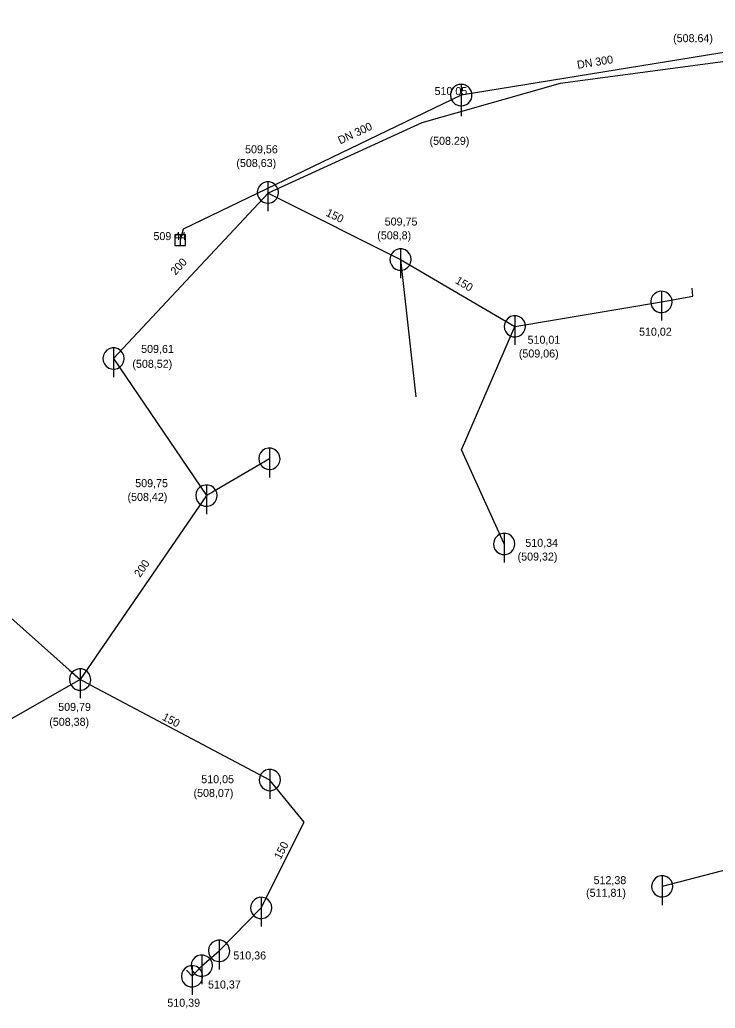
# Model space of a CAD drawing. Extents: x -476058 to -471893, y -1155786 to -1152000.
# Drawn here: x -475058.6 to -474993.4, y -1154259.7 to -1154167.1 of the extents above; entities that cross this region are included whole.
import ezdxf

# ---------------------------------------------------------------- set-up
doc = ezdxf.new("R2010")
doc.units = 0
for name, color, linetype in [('Vrstva 1', 7, 'Continuous'), ('Vrstva 10', 7, 'Continuous'), ('Vrstva 16', 7, 'Continuous'), ('Vrstva 18', 7, 'Continuous'), ('Vrstva 19', 7, 'Continuous'), ('Vrstva 3', 7, 'Continuous'), ('Vrstva 35', 7, 'Continuous'), ('Vrstva 4', 7, 'Continuous'), ('Vrstva 45', 7, 'Continuous'), ('Vrstva 50', 7, 'Continuous'), ('Vrstva 51', 7, 'Continuous')]:
    doc.layers.add(name, color=color, linetype=linetype)

msp = doc.modelspace()

# ---------------------------------------------------------------- linework, layer by layer
at = {"layer": 'Vrstva 1'}
for p, q in [((-475017.24, -1154174.14), (-475017.24, -1154174.14)), ((-475043.32, -1154186.7), (-475043.32, -1154186.7)), ((-475043.59, -1154187.73), (-475043.59, -1154187.73))]:
    msp.add_line(p, q, dxfattribs=at)
at = {"layer": 'Vrstva 10'}
for p, q in [((-475035.36, -1154182.27), (-475035.36, -1154185.018)), ((-475043.59, -1154187.23), (-475043.59, -1154188.23)), ((-475022.928, -1154188.55), (-475022.928, -1154191.298)), ((-474998.47, -1154192.52), (-474998.47, -1154195.268)), ((-475012.21, -1154194.81), (-475012.21, -1154197.558)), ((-475049.834, -1154197.823), (-475049.834, -1154200.571)), ((-475035.222, -1154207.219), (-475035.222, -1154209.967)), ((-475041.12, -1154210.67), (-475041.12, -1154213.418)), ((-475013.214, -1154215.203), (-475013.214, -1154217.951)), ((-475052.97, -1154227.9), (-475052.97, -1154230.648)), ((-475035.18, -1154237.32), (-475035.18, -1154240.068)), ((-474998.4, -1154247.28), (-474998.4, -1154250.028)), ((-475035.987, -1154249.299), (-475035.987, -1154252.047)), ((-475039.938, -1154253.32), (-475039.938, -1154256.068)), ((-475041.56, -1154254.712), (-475041.56, -1154257.46)), ((-475042.476, -1154255.709), (-475042.476, -1154258.457))]:
    msp.add_line(p, q, dxfattribs=at)
for points in [[(-475016.232, -1154174.14), (-475016.238, -1154174.035), (-475016.254, -1154173.931), (-475016.282, -1154173.829), (-475016.32, -1154173.73), (-475016.367, -1154173.636), (-475016.425, -1154173.548), (-475016.491, -1154173.466), (-475016.566, -1154173.391), (-475016.648, -1154173.325), (-475016.736, -1154173.267), (-475016.83, -1154173.22), (-475016.929, -1154173.182), (-475017.031, -1154173.154), (-475017.135, -1154173.138), (-475017.24, -1154173.132), (-475017.345, -1154173.138), (-475017.45, -1154173.154), (-475017.552, -1154173.182), (-475017.65, -1154173.22), (-475017.744, -1154173.267), (-475017.833, -1154173.325), (-475017.915, -1154173.391), (-475017.989, -1154173.466), (-475018.055, -1154173.548), (-475018.113, -1154173.636), (-475018.161, -1154173.73), (-475018.199, -1154173.829), (-475018.226, -1154173.931), (-475018.242, -1154174.035), (-475018.248, -1154174.14), (-475018.242, -1154174.245), (-475018.226, -1154174.35), (-475018.199, -1154174.452), (-475018.161, -1154174.55), (-475018.113, -1154174.644), (-475018.055, -1154174.733), (-475017.989, -1154174.815), (-475017.915, -1154174.889), (-475017.833, -1154174.955), (-475017.744, -1154175.013), (-475017.65, -1154175.061), (-475017.552, -1154175.099), (-475017.45, -1154175.126), (-475017.345, -1154175.142), (-475017.24, -1154175.148), (-475017.135, -1154175.142), (-475017.031, -1154175.126), (-475016.929, -1154175.099), (-475016.83, -1154175.061), (-475016.736, -1154175.013), (-475016.648, -1154174.955), (-475016.566, -1154174.889), (-475016.491, -1154174.815), (-475016.425, -1154174.733), (-475016.367, -1154174.644), (-475016.32, -1154174.55), (-475016.282, -1154174.452), (-475016.254, -1154174.35), (-475016.238, -1154174.245), (-475016.232, -1154174.14)], [(-475017.24, -1154173.132), (-475017.24, -1154176.108)], [(-475034.36, -1154183.27), (-475034.399, -1154182.991), (-475034.516, -1154182.734), (-475034.699, -1154182.519), (-475034.935, -1154182.365), (-475035.205, -1154182.282), (-475035.487, -1154182.278), (-475035.759, -1154182.353), (-475035.999, -1154182.501), (-475036.189, -1154182.71), (-475036.312, -1154182.964), (-475036.36, -1154183.242), (-475036.328, -1154183.523), (-475036.219, -1154183.783), (-475036.041, -1154184.002), (-475035.81, -1154184.164), (-475035.542, -1154184.254), (-475035.26, -1154184.266), (-475034.986, -1154184.198), (-475034.742, -1154184.057), (-475034.547, -1154183.853), (-475034.417, -1154183.603), (-475034.361, -1154183.326), (-475034.36, -1154183.27)], [(-475021.928, -1154189.55), (-475021.967, -1154189.271), (-475022.084, -1154189.014), (-475022.267, -1154188.799), (-475022.503, -1154188.645), (-475022.773, -1154188.562), (-475023.055, -1154188.558), (-475023.327, -1154188.633), (-475023.567, -1154188.781), (-475023.757, -1154188.99), (-475023.88, -1154189.244), (-475023.928, -1154189.522), (-475023.896, -1154189.803), (-475023.787, -1154190.063), (-475023.609, -1154190.282), (-475023.378, -1154190.444), (-475023.11, -1154190.534), (-475022.828, -1154190.546), (-475022.554, -1154190.478), (-475022.31, -1154190.337), (-475022.115, -1154190.133), (-475021.985, -1154189.883), (-475021.929, -1154189.606), (-475021.928, -1154189.55)], [(-474997.47, -1154193.52), (-474997.509, -1154193.241), (-474997.626, -1154192.984), (-474997.809, -1154192.769), (-474998.045, -1154192.615), (-474998.315, -1154192.532), (-474998.597, -1154192.528), (-474998.869, -1154192.603), (-474999.109, -1154192.751), (-474999.299, -1154192.96), (-474999.422, -1154193.214), (-474999.47, -1154193.492), (-474999.438, -1154193.773), (-474999.329, -1154194.033), (-474999.151, -1154194.252), (-474998.92, -1154194.414), (-474998.652, -1154194.504), (-474998.37, -1154194.516), (-474998.096, -1154194.448), (-474997.852, -1154194.307), (-474997.657, -1154194.103), (-474997.527, -1154193.853), (-474997.471, -1154193.576), (-474997.47, -1154193.52)], [(-475011.21, -1154195.81), (-475011.249, -1154195.531), (-475011.366, -1154195.274), (-475011.549, -1154195.059), (-475011.785, -1154194.905), (-475012.055, -1154194.822), (-475012.337, -1154194.818), (-475012.609, -1154194.893), (-475012.849, -1154195.041), (-475013.039, -1154195.25), (-475013.162, -1154195.504), (-475013.21, -1154195.782), (-475013.178, -1154196.063), (-475013.069, -1154196.323), (-475012.891, -1154196.542), (-475012.66, -1154196.704), (-475012.392, -1154196.794), (-475012.11, -1154196.806), (-475011.836, -1154196.738), (-475011.592, -1154196.597), (-475011.397, -1154196.393), (-475011.267, -1154196.143), (-475011.211, -1154195.866), (-475011.21, -1154195.81)], [(-475048.834, -1154198.823), (-475048.873, -1154198.544), (-475048.99, -1154198.287), (-475049.173, -1154198.072), (-475049.409, -1154197.918), (-475049.679, -1154197.835), (-475049.961, -1154197.831), (-475050.233, -1154197.906), (-475050.473, -1154198.054), (-475050.663, -1154198.263), (-475050.786, -1154198.517), (-475050.834, -1154198.795), (-475050.802, -1154199.076), (-475050.693, -1154199.336), (-475050.515, -1154199.555), (-475050.284, -1154199.717), (-475050.016, -1154199.807), (-475049.734, -1154199.819), (-475049.46, -1154199.751), (-475049.216, -1154199.61), (-475049.021, -1154199.406), (-475048.891, -1154199.156), (-475048.835, -1154198.879), (-475048.834, -1154198.823)], [(-475034.222, -1154208.219), (-475034.261, -1154207.94), (-475034.378, -1154207.683), (-475034.561, -1154207.468), (-475034.797, -1154207.314), (-475035.067, -1154207.231), (-475035.349, -1154207.227), (-475035.621, -1154207.302), (-475035.861, -1154207.45), (-475036.051, -1154207.659), (-475036.174, -1154207.913), (-475036.222, -1154208.191), (-475036.19, -1154208.472), (-475036.081, -1154208.732), (-475035.903, -1154208.951), (-475035.672, -1154209.113), (-475035.404, -1154209.203), (-475035.122, -1154209.215), (-475034.848, -1154209.147), (-475034.604, -1154209.006), (-475034.409, -1154208.802), (-475034.279, -1154208.552), (-475034.223, -1154208.275), (-475034.222, -1154208.219)], [(-475040.12, -1154211.67), (-475040.159, -1154211.391), (-475040.276, -1154211.134), (-475040.459, -1154210.919), (-475040.695, -1154210.765), (-475040.965, -1154210.682), (-475041.247, -1154210.678), (-475041.519, -1154210.753), (-475041.759, -1154210.901), (-475041.949, -1154211.11), (-475042.072, -1154211.364), (-475042.12, -1154211.642), (-475042.088, -1154211.923), (-475041.979, -1154212.183), (-475041.801, -1154212.402), (-475041.57, -1154212.564), (-475041.302, -1154212.654), (-475041.02, -1154212.666), (-475040.746, -1154212.598), (-475040.502, -1154212.457), (-475040.307, -1154212.253), (-475040.177, -1154212.003), (-475040.121, -1154211.726), (-475040.12, -1154211.67)], [(-475012.214, -1154216.203), (-475012.253, -1154215.924), (-475012.37, -1154215.667), (-475012.553, -1154215.452), (-475012.789, -1154215.298), (-475013.059, -1154215.215), (-475013.341, -1154215.211), (-475013.613, -1154215.286), (-475013.853, -1154215.434), (-475014.043, -1154215.643), (-475014.166, -1154215.897), (-475014.214, -1154216.175), (-475014.182, -1154216.456), (-475014.073, -1154216.716), (-475013.895, -1154216.935), (-475013.664, -1154217.097), (-475013.396, -1154217.187), (-475013.114, -1154217.199), (-475012.84, -1154217.131), (-475012.596, -1154216.99), (-475012.401, -1154216.786), (-475012.271, -1154216.536), (-475012.215, -1154216.259), (-475012.214, -1154216.203)], [(-475051.97, -1154228.9), (-475052.009, -1154228.621), (-475052.126, -1154228.364), (-475052.309, -1154228.149), (-475052.545, -1154227.995), (-475052.815, -1154227.912), (-475053.097, -1154227.908), (-475053.369, -1154227.983), (-475053.609, -1154228.131), (-475053.799, -1154228.34), (-475053.922, -1154228.594), (-475053.97, -1154228.872), (-475053.938, -1154229.153), (-475053.829, -1154229.413), (-475053.651, -1154229.632), (-475053.42, -1154229.794), (-475053.152, -1154229.884), (-475052.87, -1154229.896), (-475052.596, -1154229.828), (-475052.352, -1154229.687), (-475052.157, -1154229.483), (-475052.027, -1154229.233), (-475051.971, -1154228.956), (-475051.97, -1154228.9)], [(-475034.18, -1154238.32), (-475034.219, -1154238.041), (-475034.336, -1154237.784), (-475034.519, -1154237.569), (-475034.755, -1154237.415), (-475035.025, -1154237.332), (-475035.307, -1154237.328), (-475035.579, -1154237.403), (-475035.819, -1154237.551), (-475036.009, -1154237.76), (-475036.132, -1154238.014), (-475036.18, -1154238.292), (-475036.148, -1154238.573), (-475036.039, -1154238.833), (-475035.861, -1154239.052), (-475035.63, -1154239.214), (-475035.362, -1154239.304), (-475035.08, -1154239.316), (-475034.806, -1154239.248), (-475034.562, -1154239.107), (-475034.367, -1154238.903), (-475034.237, -1154238.653), (-475034.181, -1154238.376), (-475034.18, -1154238.32)], [(-474997.4, -1154248.28), (-474997.439, -1154248.001), (-474997.556, -1154247.744), (-474997.739, -1154247.529), (-474997.975, -1154247.375), (-474998.245, -1154247.292), (-474998.527, -1154247.288), (-474998.799, -1154247.363), (-474999.039, -1154247.511), (-474999.229, -1154247.72), (-474999.352, -1154247.974), (-474999.4, -1154248.252), (-474999.368, -1154248.533), (-474999.259, -1154248.793), (-474999.081, -1154249.012), (-474998.85, -1154249.174), (-474998.582, -1154249.264), (-474998.3, -1154249.276), (-474998.026, -1154249.208), (-474997.782, -1154249.067), (-474997.587, -1154248.863), (-474997.457, -1154248.613), (-474997.401, -1154248.336), (-474997.4, -1154248.28)], [(-475034.987, -1154250.299), (-475035.026, -1154250.02), (-475035.143, -1154249.763), (-475035.326, -1154249.548), (-475035.562, -1154249.394), (-475035.832, -1154249.311), (-475036.114, -1154249.307), (-475036.386, -1154249.382), (-475036.626, -1154249.53), (-475036.816, -1154249.739), (-475036.939, -1154249.993), (-475036.987, -1154250.271), (-475036.955, -1154250.552), (-475036.846, -1154250.812), (-475036.668, -1154251.031), (-475036.437, -1154251.193), (-475036.169, -1154251.283), (-475035.887, -1154251.295), (-475035.613, -1154251.227), (-475035.369, -1154251.086), (-475035.174, -1154250.882), (-475035.044, -1154250.632), (-475034.988, -1154250.355), (-475034.987, -1154250.299)], [(-475038.938, -1154254.32), (-475038.977, -1154254.041), (-475039.094, -1154253.784), (-475039.277, -1154253.569), (-475039.513, -1154253.415), (-475039.783, -1154253.332), (-475040.065, -1154253.328), (-475040.337, -1154253.403), (-475040.577, -1154253.551), (-475040.767, -1154253.76), (-475040.89, -1154254.014), (-475040.938, -1154254.292), (-475040.906, -1154254.573), (-475040.797, -1154254.833), (-475040.619, -1154255.052), (-475040.388, -1154255.214), (-475040.12, -1154255.304), (-475039.838, -1154255.316), (-475039.564, -1154255.248), (-475039.32, -1154255.107), (-475039.125, -1154254.903), (-475038.995, -1154254.653), (-475038.939, -1154254.376), (-475038.938, -1154254.32)], [(-475040.56, -1154255.712), (-475040.599, -1154255.433), (-475040.716, -1154255.176), (-475040.899, -1154254.961), (-475041.135, -1154254.807), (-475041.405, -1154254.724), (-475041.687, -1154254.72), (-475041.959, -1154254.795), (-475042.199, -1154254.943), (-475042.389, -1154255.152), (-475042.512, -1154255.406), (-475042.56, -1154255.684), (-475042.528, -1154255.965), (-475042.419, -1154256.225), (-475042.241, -1154256.444), (-475042.01, -1154256.606), (-475041.742, -1154256.696), (-475041.46, -1154256.708), (-475041.186, -1154256.64), (-475040.942, -1154256.499), (-475040.747, -1154256.295), (-475040.617, -1154256.045), (-475040.561, -1154255.768), (-475040.56, -1154255.712)], [(-475041.476, -1154256.709), (-475041.515, -1154256.43), (-475041.632, -1154256.173), (-475041.815, -1154255.958), (-475042.051, -1154255.804), (-475042.321, -1154255.721), (-475042.603, -1154255.717), (-475042.875, -1154255.792), (-475043.115, -1154255.94), (-475043.305, -1154256.149), (-475043.428, -1154256.403), (-475043.476, -1154256.681), (-475043.444, -1154256.962), (-475043.335, -1154257.222), (-475043.157, -1154257.441), (-475042.926, -1154257.603), (-475042.658, -1154257.693), (-475042.376, -1154257.705), (-475042.102, -1154257.637), (-475041.858, -1154257.496), (-475041.663, -1154257.292), (-475041.533, -1154257.042), (-475041.477, -1154256.765), (-475041.476, -1154256.709)]]:
    msp.add_lwpolyline(points, dxfattribs=at)
msp.add_lwpolyline([(-475044.09, -1154187.23), (-475044.09, -1154188.23), (-475043.09, -1154188.23), (-475043.09, -1154187.23)], close=True, dxfattribs=at)
at = {"layer": 'Vrstva 35'}
msp.add_lwpolyline([(-474850.38, -1154154.67), (-474890.71, -1154158.68), (-474940.09, -1154163.87), (-474990.69, -1154169.83), (-475017.24, -1154174.14), (-475043.32, -1154186.7), (-475043.59, -1154187.73)], dxfattribs=at)
at = {"layer": 'Vrstva 45'}
for p, q in [((-474988.47, -1154170.45), (-475007.973, -1154173.048)), ((-475007.973, -1154173.048), (-475020.945, -1154176.758)), ((-475020.945, -1154176.758), (-475035.347, -1154183.321))]:
    msp.add_line(p, q, dxfattribs=at)
for points in [[(-475035.347, -1154183.321), (-475049.834, -1154198.823)], [(-475049.834, -1154198.823), (-475041.12, -1154211.67)], [(-475041.12, -1154211.67), (-475052.97, -1154228.9)], [(-475052.97, -1154228.9), (-475066.31, -1154236.52)]]:
    msp.add_lwpolyline(points, dxfattribs=at)
at = {"layer": 'Vrstva 50'}
msp.add_line((-474962.057, -1154238.955), (-474998.4, -1154248.28), dxfattribs=at)
for points in [[(-475035.347, -1154183.321), (-475034.699, -1154183.634), (-475022.928, -1154189.55)], [(-475022.928, -1154189.55), (-475012.21, -1154195.81), (-474998.47, -1154193.52)], [(-475013.214, -1154216.203), (-475017.205, -1154207.368), (-475012.21, -1154195.81)], [(-475035.222, -1154208.219), (-475040.551, -1154211.337), (-475041.12, -1154211.67)], [(-475063.81, -1154219.28), (-475053.983, -1154228.001), (-475052.97, -1154228.9)], [(-475035.18, -1154238.32), (-475051.919, -1154229.456), (-475052.97, -1154228.9)], [(-475035.987, -1154250.299), (-475031.954, -1154242.258), (-475035.18, -1154238.32)], [(-475042.992, -1154256.133), (-475042.476, -1154256.709), (-475041.56, -1154255.712), (-475039.938, -1154254.32), (-475035.987, -1154250.299)]]:
    msp.add_lwpolyline(points, dxfattribs=at)
at = {"layer": 'Vrstva 51'}
msp.add_line((-475022.928, -1154189.55), (-475021.497, -1154202.409), dxfattribs=at)
msp.add_lwpolyline([(-474998.47, -1154193.52), (-474995.525, -1154192.996), (-474995.595, -1154192.236)], dxfattribs=at)

# ---------------------------------------------------------------- texts
at = {"layer": 'Vrstva 16'}
for rotation, p in [(9.22069, (-475006.316, -1154171.688)), (25.07728, (-475028.584, -1154178.773))]:
    msp.add_text('DN 300', height=0.75, rotation=rotation, dxfattribs=at).set_placement(p)
at = {"layer": 'Vrstva 18'}
for rotation, p in [(46.89045, (-475044.026, -1154191.064)), (55.4816, (-475047.347, -1154219.389))]:
    msp.add_text('200 ', height=0.75, rotation=rotation, dxfattribs=at).set_placement(p)
at = {"layer": 'Vrstva 19'}
for rotation, p in [(334.05487, (-475029.99, -1154185.416)), (328.70329, (-475017.865, -1154191.714)), (332.09691, (-475045.343, -1154232.638)), (61.75128, (-475034.179, -1154245.826))]:
    msp.add_text('150 ', height=0.75, rotation=rotation, dxfattribs=at).set_placement(p)
at = {"layer": 'Vrstva 3'}
for s, p in [('510 05 ', (-475019.74, -1154174.14)), ('509,56', (-475037.5, -1154179.596)), ('509,75', (-475024.412, -1154186.368)), ('509 44 ', (-475046.09, -1154187.73)), ('510,02', (-475000.568, -1154196.689)), ('510,01', (-475011.021, -1154197.441)), ('509,61', (-475047.246, -1154198.301)), ('509,75', (-475047.798, -1154210.879)), ('510,34', (-475011.23, -1154216.47)), ('509,79', (-475055.02, -1154231.843)), ('510,05', (-475041.608, -1154238.616)), ('512,38', (-475004.834, -1154248.076)), ('510,36', (-475038.6, -1154255.129)), ('510,37', (-475040.974, -1154257.852)), ('510,39', (-475044.788, -1154259.56))]:
    msp.add_text(s, height=0.75, dxfattribs=at).set_placement(p)
at = {"layer": 'Vrstva 4'}
for s, p in [('(508.64) ', (-474997.377, -1154169.186)), ('(508.29) ', (-475020.209, -1154178.804)), ('(508,63)', (-475038.32, -1154180.884)), ('(508,8)', (-475025.109, -1154187.657)), ('(509,06)', (-475011.839, -1154198.73)), ('(508,52)', (-475048.064, -1154199.697)), ('(508,42)', (-475048.523, -1154212.168)), ('(509,32)', (-475011.954, -1154217.758)), ('(508,38)', (-475055.859, -1154233.239)), ('(508,07)', (-475042.333, -1154239.904)), ('(511,81)', (-475005.534, -1154249.257))]:
    msp.add_text(s, height=0.75, dxfattribs=at).set_placement(p)

doc.saveas('drawing.dxf')
